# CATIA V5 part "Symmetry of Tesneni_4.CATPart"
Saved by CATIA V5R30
Part number: Symmetry of Tesneni_4
Bounding box of the stored display mesh (mm): x 0 to 1.2, y -6 to 6, z -6 to 6
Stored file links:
  E:\Bakalarka\Model\Forma_v7\Symmetry of Tesneni_4.CATPart
  E:\Bakalarka\Model\Forma_v7\Tesneni.CATPart
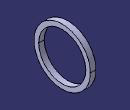
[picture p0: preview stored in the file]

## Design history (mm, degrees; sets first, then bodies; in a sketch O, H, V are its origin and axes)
Body1 (main body)
  Body2 "Body from original PartBody"
    Solid1: linked copy from another document
  Assemble1: tool Body2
